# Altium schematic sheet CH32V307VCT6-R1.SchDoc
size 457 x 287 mm; SheetNumber: 0; SheetTotal: 0
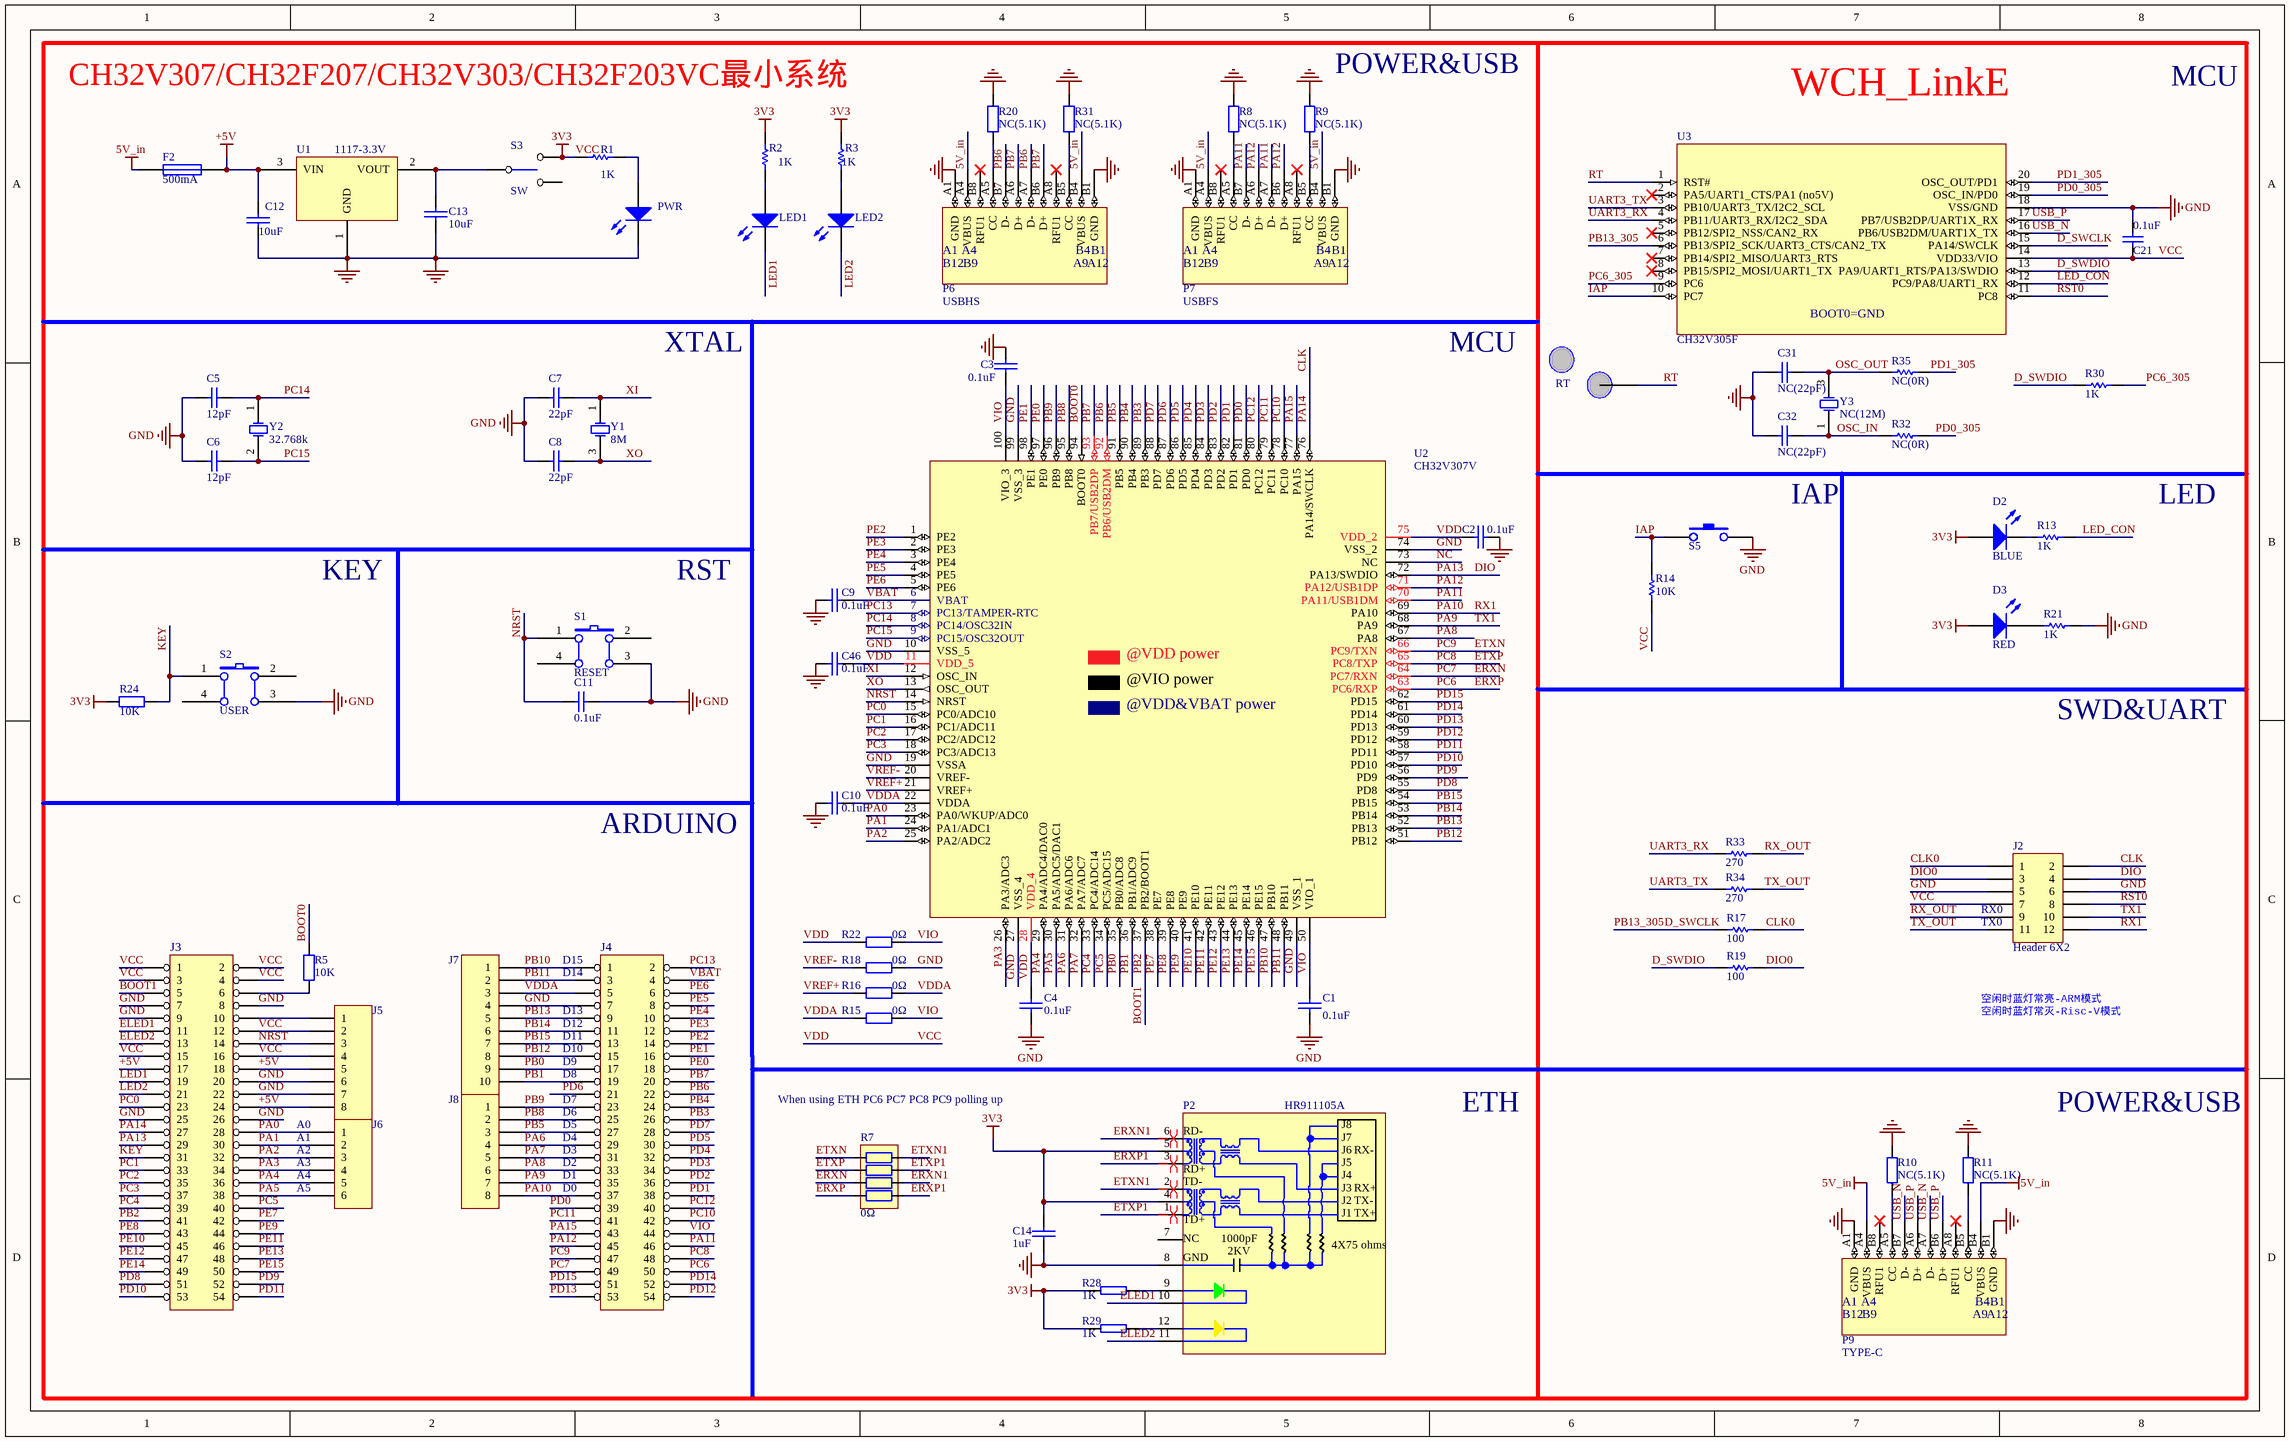
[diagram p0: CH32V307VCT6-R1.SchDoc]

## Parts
C1  0.1uF  [0603_C]
C2  0.1uF  [0603_C]
C3  0.1uF  [0603_C]
C4  0.1uF  [0603_C]
C5  12pF  [0603_C]
C6  12pF  [0603_C]
C7  22pF  [0603_C]
C8  22pF  [0603_C]
C9  0.1uF  [0603_C]
C10  0.1uF  [0603_C]
C11  0.1uF  [0603_C]
C12  10uF  [3216_C]
C13  10uF  [3216_C]
C14  1uF  [0603_C]
C21  0.1uF  [0603_C]
C31  NC(22pF)  [0603_C]
C32  NC(22pF)  [0603_C]
C46  0.1uF  [0603_C]
D2  BLUE  [0603+]
D3  RED  [0603+]
F2  500mA  [0805]
J2  Header 6X2  [IDC12-2.54mm]
J3  HEADER 27x2  [IDC54-2.54MM]  (value not drawn)
J4  HEADER 27x2  [IDC54-2.54MM]  (value not drawn)
J5  Header 8  [SIP8-2.54mm]  (value not drawn)
J6  Header 6  [SIP6-2.54MM]  (value not drawn)
J7  Header 10  [SIP10-2.54mm]  (value not drawn)
J8  Header 8  [SIP8-2.54mm]  (value not drawn)
LED1  LED1   blue  [0603+]  (value not drawn)
LED2  LED2  blue  [0603+]  (value not drawn)
P2  HR911105A  [HR911105A]
P6  USBHS  [TYPE-C-Receptacle-2.0]
P7  USBFS  [TYPE-C-Receptacle-2.0]
P9  TYPE-C  [TYPE-C-Receptacle-2.0]
PWR  POWER  red  [0603+]  (value not drawn)
R1  1K  [0603]
R2  1K  [0603]
R3  1K  [0603]
R5  10K  [0603]
R7  0Ω  [RCA-8P4R-0603]
R8  NC(5.1K)  [0603]
R9  NC(5.1K)  [0603]
R10  NC(5.1K)  [0603]
R11  NC(5.1K)  [0603]
R13  1K  [0603]
R14  10K  [0603]
R15  0Ω  [0603]
R16  0Ω  [0603]
R17  100  [0603]
R18  0Ω  [0603]
R19  100  [0603]
R20  NC(5.1K)  [0603]
R21  1K  [0603]
R22  0Ω  [0603]
R24  10K  [0603]
R28  1K  [0603]
R29  1K  [0603]
R30  1K  [0603]
R31  NC(5.1K)  [0603]
R32  NC(0R)  [0603]
R33  270  [0603]
R34  270  [0603]
R35  NC(0R)  [0603]
RT  Testpoint  [TESTPOINT1]  (value not drawn)
S1  RESET  [KEYX]
S2  USER  [KEYX]
S3  SW  [SW1]
S5  KEY  [贴片按键]  (value not drawn)
U1  1117-3.3V  [SOT-223]
U2  CH32V307V  [LQFP100]
U3  CH32V305F  [TSSOP20]
Y1  8M  [XT3225]
Y2  32.768k  [FC-135]
Y3  NC(12M)  [XT3225]

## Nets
5V_in: F2.1 P6.A4(VBUS) P6.B4(VBUS) P7.A4(VBUS) P7.B4(VBUS) P9.A4(VBUS) P9.B4(VBUS)
+5V: C12.1 F2.2 J3.17 J3.18 J3.24 J5.5 J5.8 U1.3(VIN)
GND: C1.1 C2.1 C3.2 C4.1 C5.2 C6.2 C7.1 C8.1 C9.1 C10.1 C11.1 C12.2 C13.2 C14.1 C21.2 C31.1 C32.1 C46.2 J2.5 J2.6 J3.7 J3.8 J3.9 J3.20 J3.22 J3.25 J3.26 J4.7 J5.6 J5.7 J7.4 P2.8 P6.A1(GND) P6.B1(GND) P7.A1(GND) P7.B1(GND) P9.A1(GND) P9.B1(GND) PWR.2(K) R8.1 R9.1 R10.2 R11.2 R18.1 R20.1 R21.1 R31.1 S1.3(B1) S2.3(B1) S5.2 U1.1(GND) U2.10(VSS_5) U2.19(VSSA) U2.27(VSS_4) U2.49(VSS_1) U2.74(VSS_2) U2.99(VSS_3) U3.18(VSS/GND)
VCC: C2.2 C4.2 C14.2 C21.1 C46.1 D2.1(A) D3.1(A) J2.7 J3.1 J3.2 J3.3 J3.4 J3.12 J3.15 J3.16 J5.2 J5.4 P2.4 P2.5 R1.2 R2.1 R3.1 R14.2 R22.2 R24.2 R28.1 R29.1 S3.3 U2.11(VDD_5) U2.28(VDD_4) U2.75(VDD_2) U3.14(VDD33/VIO)  [also labelled 3V3, VDD]
BOOT0: R5.2 U2.94(BOOT0)
BOOT1: J3.5 J3.41 U2.37(PB2/BOOT1)  [also labelled PB2]
CLK: J2.2 J3.27 U2.76(PA14/SWCLK)  [also labelled PA14]
CLK0: J2.1 R17.1
D_SWCLK: R17.2 U3.6(PB13/SPI2_SCK/UART3_CTS/CAN2_TX) U3.15(PA14/SWCLK)  [also labelled PB13_305]
D_SWDIO: R19.2 R30.1 U3.13(PA9/UART1_RTS/PA13/SWDIO)
DIO: J2.4 J3.29 U2.72(PA13/SWDIO)  [also labelled PA13]
DIO0: J2.3 R19.1
ELED1: J3.11 P2.10
ELED2: J3.13 P2.11
ERXN: J4.49 R7.3 U2.64(PC7/RXN)  [also labelled PC7]
ERXN1: P2.6 R7.6
ERXP: J4.50 R7.4 U2.63(PC6/RXP)  [also labelled PC6]
ERXP1: P2.3 R7.5
ETXN: J4.47 R7.1 U2.66(PC9/TXN)  [also labelled PC9]
ETXN1: P2.2 R7.8
ETXP: J4.48 R7.2 U2.65(PC8/TXP)  [also labelled PC8]
ETXP1: P2.1 R7.7
IAP: R14.1 S5.1 U3.10(PC7)
KEY: J3.31 R24.1 S2.1(A0)
LED1: J3.19 LED1.2(K)
LED2: J3.21 LED2.2(K)
LED_CON: R13.1 U3.12(PC9/PA8/UART1_RX)
NC: U2.73(NC)
NRST: C11.2 J3.14 J5.3 S1.1(A0) U2.14(NRST)
OSC_IN: C32.2 R32.2 Y3.1(OSC1)
OSC_OUT: C31.2 R35.2 Y3.3(OSC2)
PA0: J3.28 J6.1 U2.23(PA0/WKUP/ADC0)
PA1: J3.30 J6.2 U2.24(PA1/ADC1)
PA2: J3.32 J6.3 U2.25(PA2/ADC2)
PA3: J3.34 J6.4 U2.26(PA3/ADC3)
PA4: J3.36 J6.5 U2.29(PA4/ADC4/DAC0)
PA5: J3.38 J6.6 U2.30(PA5/ADC5/DAC1)
PA6: J4.29 J8.4 U2.31(PA6/ADC6)
PA7: J4.31 J8.5 U2.32(PA7/ADC7)
PA8: J4.33 J8.6 U2.67(PA8)
PA9: J2.10 J4.35 J8.7 U2.68(PA9)  [also labelled TX1]
PA10: J2.12 J4.37 J8.8 U2.69(PA10)  [also labelled RX1]
PA11: J4.46 P7.A7(D-) P7.B7(D-) U2.70(PA11/USB1DM)
PA12: J4.45 P7.A6(D+) P7.B6(D+) U2.71(PA12/USB1DP)
PA15: J4.43 U2.77(PA15)
PB0: J4.17 J7.9 U2.35(PB0/ADC8)
PB1: J4.19 J7.10 U2.36(PB1/ADC9)
PB3: J4.26 U2.89(PB3)
PB4: J4.24 U2.90(PB4)
PB5: J4.27 J8.3 U2.91(PB5)
PB6: J4.22 P6.A7(D-) P6.B7(D-) U2.92(PB6/USB2DM)
PB7: J4.20 P6.A6(D+) P6.B6(D+) U2.93(PB7/USB2DP)
PB8: J4.25 J8.2 U2.95(PB8)
PB9: J4.23 J8.1 U2.96(PB9)
PB10: J4.1 J7.1 U2.47(PB10)
PB11: J4.3 J7.2 U2.48(PB11)
PB12: J4.15 J7.8 U2.51(PB12)
PB13: J4.9 J7.5 U2.52(PB13)
PB14: J4.11 J7.6 U2.53(PB14)
PB15: J4.13 J7.7 U2.54(PB15)
PC0: J3.23 U2.15(PC0/ADC10)
PC1: J3.33 U2.16(PC1/ADC11)
PC2: J3.35 U2.17(PC2/ADC12)
PC3: J3.37 U2.18(PC3/ADC13)
PC4: J3.39 U2.33(PC4/ADC14)
PC5: J3.40 U2.34(PC5/ADC15)
PC6_305: R30.2 U3.9(PC6)
PC10: J4.42 U2.78(PC10)
PC11: J4.41 U2.79(PC11)
PC12: J4.40 U2.80(PC12)
PC13: J4.2 U2.7(PC13/TAMPER-RTC)
PC14: C5.1 U2.8(PC14/OSC32IN) Y2.1(OSC1)
PC15: C6.1 U2.9(PC15/OSC32OUT) Y2.2(OSC2)
PD0: J4.39 U2.81(PD0)
PD0_305: R32.1 U3.19(OSC_IN/PD0)
PD1: J4.38 U2.82(PD1)
PD1_305: R35.1 U3.20(OSC_OUT/PD1)
PD2: J4.36 U2.83(PD2)
PD3: J4.34 U2.84(PD3)
PD4: J4.32 U2.85(PD4)
PD5: J4.30 U2.86(PD5)
PD6: J4.21 U2.87(PD6)
PD7: J4.28 U2.88(PD7)
PD8: J3.51 U2.55(PD8)
PD9: J3.52 U2.56(PD9)
PD10: J3.53 U2.57(PD10)
PD11: J3.54 U2.58(PD11)
PD12: J4.54 U2.59(PD12)
PD13: J4.53 U2.60(PD13)
PD14: J4.52 U2.61(PD14)
PD15: J4.51 U2.62(PD15)
PE0: J4.18 U2.97(PE0)
PE1: J4.16 U2.98(PE1)
PE2: J4.14 U2.1(PE2)
PE3: J4.12 U2.2(PE3)
PE4: J4.10 U2.3(PE4)
PE5: J4.8 U2.4(PE5)
PE6: J4.6 U2.5(PE6)
PE7: J3.42 U2.38(PE7)
PE8: J3.43 U2.39(PE8)
PE9: J3.44 U2.40(PE9)
PE10: J3.45 U2.41(PE10)
PE11: J3.46 U2.42(PE11)
PE12: J3.47 U2.43(PE12)
PE13: J3.48 U2.44(PE13)
PE14: J3.49 U2.45(PE14)
PE15: J3.50 U2.46(PE15)
RST0: J2.8 U3.11(PC8)
RT: RT.1(point) U3.1(RST#)
RX_OUT: J2.9 R33.1
TX_OUT: J2.11 R34.1
UART3_RX: R33.2 U3.4(PB11/UART3_RX/I2C2_SDA)
UART3_TX: R34.2 U3.3(PB10/UART3_TX/I2C2_SCL)
USB_N: P9.A7(D-) P9.B7(D-) U3.16(PB6/USB2DM/UART1X_TX)
USB_P: P9.A6(D+) P9.B6(D+) U3.17(PB7/USB2DP/UART1X_RX)
VBAT: C9.2 J4.4 U2.6(VBAT)
VDDA: C10.2 J4.5 J7.3 R15.2 R16.1 U2.22(VDDA)
VIO: C1.2 C3.1 J4.44 R15.1 R22.1 U2.50(VIO_1) U2.100(VIO_3)
VREF+: R16.2 U2.21(VREF+)
VREF-: R18.2 U2.20(VREF-)
XI: C7.2 U2.12(OSC_IN) Y1.1(OSC1)
XO: C8.2 U2.13(OSC_OUT) Y1.3(OSC2)
NetC13_1: C13.1 S3.1 U1.2(VOUT)
NetD2_2: D2.2(K) R13.2
NetD3_2: D3.2(K) R21.2
NetJ3_6: J3.6 R5.1
NetJ3_10: J3.10 J5.1
NetLED1_1: LED1.1(A) R2.2
NetLED2_1: LED2.1(A) R3.2
NetP2_9: P2.9 R28.2
NetP2_12: P2.12 R29.2
NetP6_A5: P6.A5(CC) R20.2
NetP6_B5: P6.B5(CC) R31.2
NetP7_A5: P7.A5(CC) R8.2
NetP7_B5: P7.B5(CC) R9.2
NetP9_A5: P9.A5(CC) R10.1
NetP9_B5: P9.B5(CC) R11.1
NetPWR_1: PWR.1(A) R1.1

Not connected (* = marked no-connect by the designer): P2 7; P6 A8(RFU1)* B8(RFU1)*; P7 A8(RFU1)* B8(RFU1)*; P9 A8(RFU1)* B8(RFU1)*; S1 2(B0) 4(A1); S2 2(B0) 4(A1); S3 2; U3 2(PA5/UART1_CTS/PA1_(no5V))* 5(PB12/SPI2_NSS/CAN2_RX)* 7(PB14/SPI2_MISO/UART3_RTS)* 8(PB15/SPI2_MOSI/UART1_TX)*

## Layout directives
differential pair: ERXN1, ERXP1, ETXN1, ETXP1

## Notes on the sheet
- CH32V307/CH32F207/CH32V303/CH32F203VC最小系统
- (near R9) POWER&USB
- WCH_LinkE
- MCU
- XTAL
- IAP
- LED
- KEY
- RST
- SWD&UART
- ARDUINO
- (near J2) RX0
- (near J2) TX0
- (near J4) D13
- (near J4) D14
- (near J4) D15
- 空闲时蓝灯常亮-ARM模式
- 空闲时蓝灯常灭-Risc-V模式
- (near J4) D8
- (near J4) D9
- (near J4) D10
- (near J4) D11
- (near J4) D12
- A0
- A1
- (near J4) D4
- (near J4) D5
- (near J4) D6
- (near J4) D7
- When using ETH PC6 PC7 PC8 PC9 polling up
- ETH
- POWER&USB
- (near J6) A2
- (near J6) A3
- (near J6) A4
- (near J6) A5
- (near J4) D0
- (near J4) D1
- (near J4) D2
- (near J4) D3

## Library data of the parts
C1-C4 C9 C10 C12-C14 C46 = CAP: Capacitor
C5-C8 C11 C21 C31 C32 = Cap: Capacitor
D2 D3 = D0603: Typical RED, GREEN, YELLOW, AMBER GaAs LED
F2 = FUSE1: Fuse
J2 = Header 6X2: Header, 6-Pin, Dual row
J3 J4 = HEADER 27x2: Header, 27-Pin, Dual row
J5 J8 = Header 8: Header, 8-Pin
J6 = Header 6: Header, 6-Pin
J7 = Header 10: Header, 10-Pin
LED1 LED2 PWR = LED0: Typical INFRARED GaAs LED
P6 P7 P9 = TYPE-C1
R1-R3 = Res Semi: Semiconductor Resistor
R5 R8-R11 R15 R16 R18 R20 R22 R24 R31 = Res2: Resistor
R7 = R-8P4R: 贴片网络排阻; 版权归属: 源创客
R13 R14 R17 R19 R21 R30 R32-R35 = R0603: Resistor
R28 R29 = RES
RT = Testpoint: 测试点
S1 S2 = SW PUSHBUTTON: SE PUSHBUTTON
U2 = CH32V307V: RISC-V FPU HD-MCU, 144MHz, USB_480M, USB OTG, 1000M Ethernet MAC, 2*CAN, FSMC+DVP
U3 = CH32V305F: RISC-V FPU HD-MCU, 144MHz, USB_480M, CAN, UART*2, SPI
Y1-Y3 = XTAL: Crystal Oscillator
